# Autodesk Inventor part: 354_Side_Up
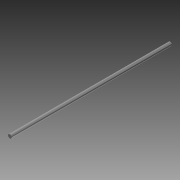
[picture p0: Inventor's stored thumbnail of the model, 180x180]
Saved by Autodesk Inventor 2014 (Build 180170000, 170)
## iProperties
Created: 2013-12
Part Number: 354_Side_Up
Material: Stainless Steel
Document SubType Name: Modeling
Designer: Bram
Density: 8.08 g/cm^3
Appearance: Semi-Polished
Author: Bram
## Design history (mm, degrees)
sketch "Sketch1"
  geometry: C1 r 4 at (0, 0); 1 further point
  constraints: 1 centre point, 1 coincident
  dimensions: "d0" = 8 diameter of C1
extrude "Extrusion1" new body sketch "Sketch1" distance "d1" = 354; taper "d2" = 0 deg
body "Solid1"
